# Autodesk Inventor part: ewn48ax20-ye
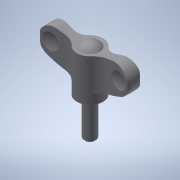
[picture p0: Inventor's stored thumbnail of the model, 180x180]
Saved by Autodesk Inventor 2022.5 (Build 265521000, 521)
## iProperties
Created: 2016-12
Part Number: ewn48ax20-ye
Material: 一般
Document SubType Name: Modeling
Designer: imaocorp
Density: 1 g/cm^3
Appearance: 既定
Author: imaocorp
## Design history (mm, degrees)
node "ewn48ax20-ye.x_t1"
node "ewn48ax20-ye"
node "Base1"
